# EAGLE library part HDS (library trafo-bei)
Transformer Dual primary 115/230V 50/60HZ 10.0VA Source: BEI_DDS30F_10VA_size.pdf
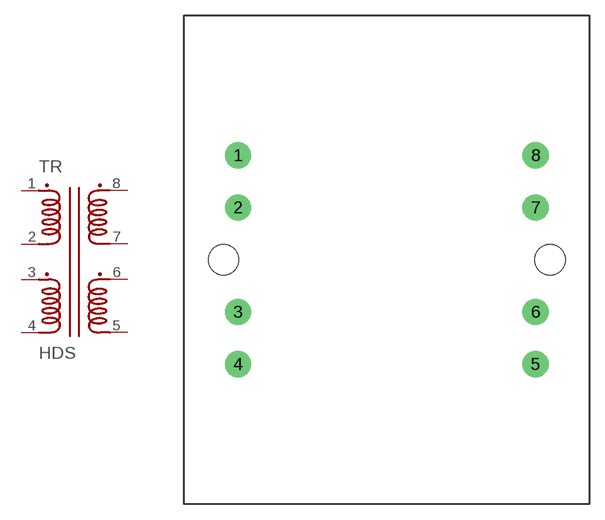
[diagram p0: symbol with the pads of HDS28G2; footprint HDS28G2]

Designator prefix TR

## HDS28G2 (OC_FARNELL: unknown; OC_NEWARK: unknown)  [HDS28G2]
1  P1.1  pas
2  P1.2  pas
3  P2.1  pas
4  P2.2  pas
5  S2.2  pas
6  S2.1  pas
7  S1.2  pas
8  S1.1  pas

## Footprint HDS28G2 (pad centres in mm)
Transformer Dual primary 115/230V 50/60HZ 10.0VA Source: BEI_DDS30F_10VA_size.pdf
drill 1.27 pad 2.54 round: 1 -14.478,10.16; 2 -14.478,5.08; 3 -14.478,-5.08; 4 -14.478,-10.16; 5 14.478,-10.16; 6 14.478,-5.08; 7 14.478,5.08; 8 14.478,10.16
hole 2.946 at -15.875,0
hole 2.946 at 15.875,0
